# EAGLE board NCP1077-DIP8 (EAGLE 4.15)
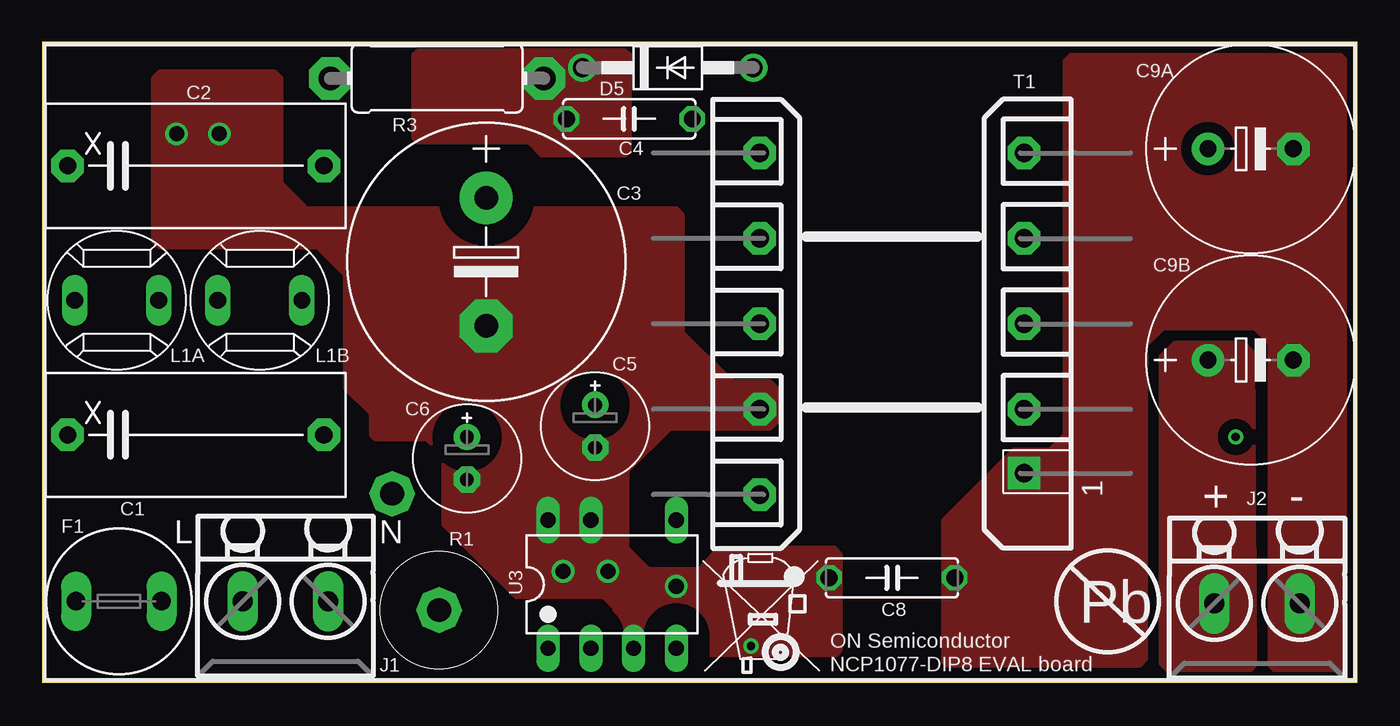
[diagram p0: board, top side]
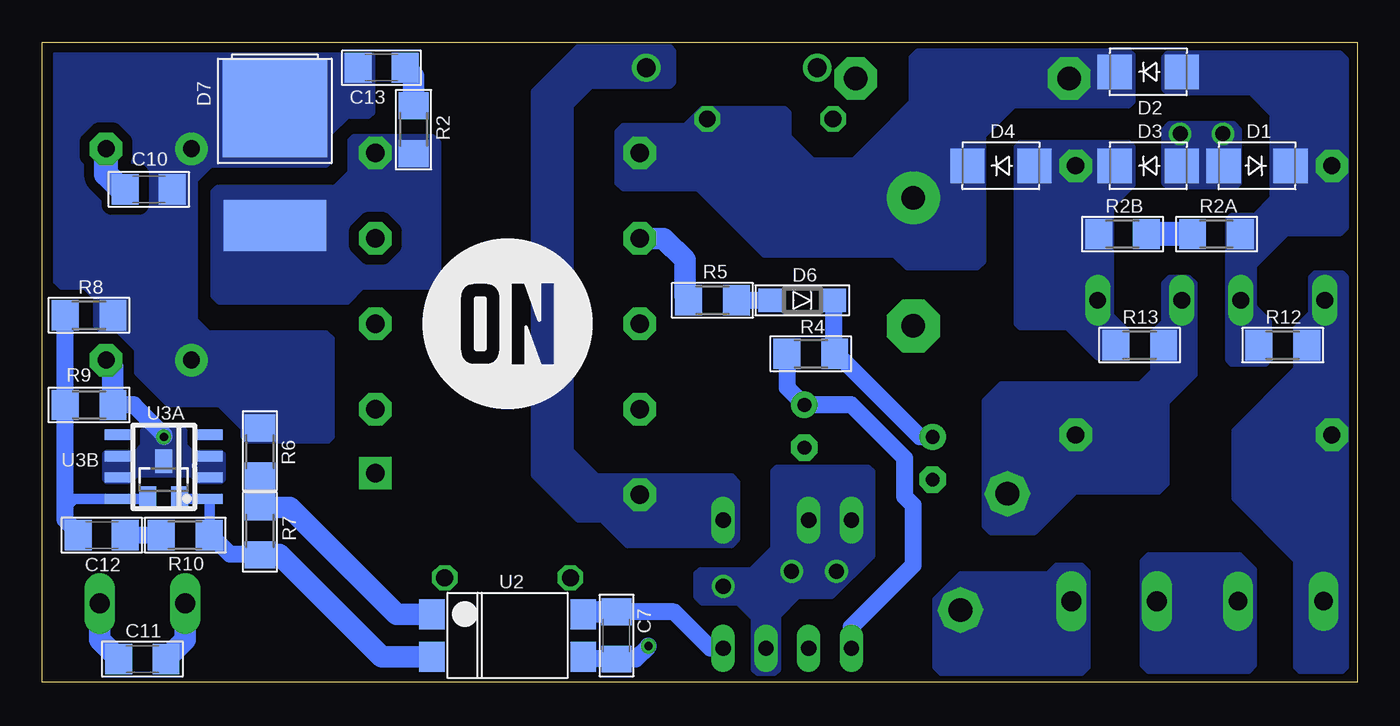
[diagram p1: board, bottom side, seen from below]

Size 78.23 x 38.1 mm. Coordinates in mm from the lower left corner, seen from the top.
Outline: 0,0 78.23,0 78.23,38.1 0,38.1 0,0
Copper layers (1*16): Top 0.035mm / dielectric 1.5mm / Bottom 0.035mm
Design rules "default": minimum track width 10mil, minimum drill 19mil, track to track 8mil, track to pad 8mil, pad to pad 8mil, via to via 8mil, smd to smd 8mil, copper to edge 5mil, drill to drill 8mil, minimum pad ring 10mil, minimum via ring 8mil, stop-mask expansion 4mil, vias tented up to drill 0mil, thermal gap 10mil

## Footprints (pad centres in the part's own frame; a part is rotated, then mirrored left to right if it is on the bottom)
XC18B7.5LS15 = drill 1.016 pad 1.93 octagon: 1 -7.62,0; 2 7.62,0
E7,5-16 = drill 1.4 pad 3.15 round: + -3.81,0 | drill 1.4 pad 3.15 octagon: - 3.81,0
C075-025X080 = drill 1 octagon: 1 -3.74,0; 2 3.74,0
E2.5-6.5 = drill 0.813 pad 1.575 round: + -1.27,0 | drill 0.813 pad 1.575 octagon: - 1.27,0
C1206 = smd 1.6 x 1.8: 1 -1.4,0; 2 1.4,0
E5-12,5 = drill 1 pad 1.93 round: + -2.54,0 | drill 1 pad 1.93 octagon: - 2.54,0
SMA-DIODE = smd 2.032 x 2.032: A 1.994,0; C -1.994,0
DO41-10 = drill 1.118 round: A 5.08,0; C -5.08,0
SOD123 = smd 1.4 x 1.4: A 1.9,0; C -1.9,0
DPAK-SCHOTTKY-2PADS = smd 3.048 x 6.096: 1 2.54,0 | smd 5.791 x 6.198: 4 -4.42,0
TR5 = drill 1.1 pad 1.778 long: 1 -2.54,0; 2 2.54,0
2-PIN = drill 1.2 long: + -2.54,0; - 2.54,0
WE-7447728215 = drill 1 long: P$1 -2.5,0; P$2 2.5,0
3W-STAND-UP = drill 1.4 pad 2.54 octagon: P$1 3.75,0; P$2 -3.71,0
R1206 = smd 1.6 x 1.803: 1 -1.422,0; 2 1.422,0
0411/12 = drill 1.4 pad 2.54 octagon: 1 -6.35,0; 2 6.35,0
E25/10/6-10P = drill 1.1 pad 1.93 square: 1 -8.89,-7.85 | drill 1.1 pad 1.93 octagon: 2 -5.08,-7.85; 3 0,-7.85; 4 5.08,-7.85; 5 10.16,-7.85; 6 10.16,7.85; 7 5.08,7.85; 8 0,7.85; 9 -5.08,7.85; 10 -10.16,7.85
4PIN-SURFMOUNT-OPTO = smd 1.524 x 1.778: 1 4.496,-1.27; 2 4.496,1.27; 3 -4.496,1.27; 4 -4.496,-1.27
DIP07 = drill 0.9 long: 1 -3.81,-3.81; 2 -1.27,-3.81; 3 1.27,-3.81; 4 3.81,-3.81; 5 3.81,3.81; 7 -1.27,3.81; 8 -3.81,3.81
SOT-23 = smd 1 x 1.4: 1 -0.95,-1.1; 2 0.95,-1.1; 3 0,1.1
SOIC-8 = smd 0.61 x 1.524: 1 -1.905,-2.743; 2 -0.635,-2.743; 3 0.635,-2.743; 4 1.905,-2.743; 5 1.905,2.743; 6 0.635,2.743; 7 -0.635,2.743; 8 -1.905,2.743

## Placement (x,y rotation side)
C1  100nF  [XC18B7.5LS15]  9.14,14.73 0 top
C2  100nF  [XC18B7.5LS15]  9.14,30.73 0 top
C3  22uF  [E7,5-16]  26.42,25.02 270 top
C4  1nF  [C075-025X080]  34.93,33.53 180 top
C5  22uF  [E2.5-6.5]  32.89,15.24 270 top
C6  4.7uF  [E2.5-6.5]  25.27,13.34 270 top
C7  1nF  [C1206]  44.07,2.79 270 bottom
C8  1nF  [C075-025X080]  50.55,6.22 0 top
C9A  1000uF  [E5-12,5]  71.88,31.75 0 top
C9B  1000uF  [E5-12,5]  71.88,19.18 0 top
C10  100nF  [C1206]  71.88,29.34 180 bottom
C11  100nF  [C1206]  72.26,1.4 180 bottom
C12  100nF  [C1206]  74.68,8.76 180 bottom
C13  1nF  [C1206]  58.04,36.58 180 bottom
D1  MRA4007  [SMA-DIODE]  5.97,30.73 180 bottom
D2  MRA4007  [SMA-DIODE]  12.45,36.32 0 bottom
D3  MRA4007  [SMA-DIODE]  12.45,30.73 0 bottom
D4  MRA4007  [SMA-DIODE]  21.21,30.73 0 bottom
D5  1N4937  [DO41-10]  37.21,36.58 0 top
D6  MMSD4148A  [SOD123]  33.02,22.73 180 bottom
D7  MBRS3100  [DPAK-SCHOTTKY-2PADS]  64.39,29.72 270 bottom
E$2  [ON2]  50.55,21.34 0 bottom
F1  1.5A  [TR5]  4.57,4.83 180 top
J1  [2-PIN]  14.48,4.83 0 top
J2  [2-PIN]  72.26,4.7 0 top
L1A  1mH  [WE-7447728215]  4.45,22.73 0 top
L1B  1mH  [WE-7447728215]  12.95,22.73 0 top
R1  4.3/3W  [3W-STAND-UP]  22.23,7.75 112 top
R2  47  [R1206]  56.13,32.89 270 bottom
R2A  3.3M  [R1206]  8.38,26.67 0 bottom
R2B  3.3M  [R1206]  13.97,26.67 0 bottom
R3  68K  [0411/12]  23.5,35.94 180 top
R4  2.7K  [R1206]  32.51,19.56 180 bottom
R5  10  [R1206]  38.35,22.73 0 bottom
R6  1K  [R1206]  65.28,13.72 270 bottom
R7  10K  [R1206]  65.28,9.02 270 bottom
R8  82.5K  [R1206]  75.44,21.84 0 bottom
R9  10K  [R1206]  75.44,16.51 180 bottom
R10  21.5K  [R1206]  69.72,8.76 0 bottom
R12  5.6K  [R1206]  4.45,20.07 0 bottom
R13  5.6K  [R1206]  12.95,20.07 0 bottom
T1  [E25/10/6-10P]  50.55,21.34 90 top
U2  PS2561L_1  [4PIN-SURFMOUNT-OPTO]  50.55,2.79 180 bottom
U3  NCP1077  [DIP07]  33.91,5.84 0 top
U3A  NCP431A  [SOT-23]  70.99,12.07 0 bottom
U3B  NCP431A  [SOIC-8]  70.99,12.83 90 bottom
U$3  [WEEE_SMALL]  42.93,1.91 0 top

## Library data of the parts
C1-C8 C9A C9B C10-C13 R2 R2A R2B R3-R10 R12 R13 = rcl
D1-D7 = diode
E$2 = loga
F1 = fuse
J1 J2 = My CONNECTOR lib
L1A L1B = MY  INDUCTOR Lib
R1 = resistor-power
T1 = My X-former
U2 = optocoupler
U3 U3A U3B = My IC Lib
U$3 = My Sign Lib

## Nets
N$1: C1.1 F1.2 L1A.P$1 R12.2
N$2: F1.1 J1.+
N$3: C2.1 D1.C D2.A L1A.P$2 R2A.2 R12.1
N$4: C1.2 L1B.P$1 R1.P$1 R13.2
N$5: J1.- R1.P$2
N$6: C2.2 D3.C D4.A L1B.P$2 R2B.1 R13.1
N$7: R2A.1 R2B.2
N$8: C13.1 R2.1
N$9: D5.A T1.10 U3.5
N$10: C3.+ C4.1 D2.C D4.C R3.2 T1.6
N$11: C4.2 D5.C R3.1
N$13: C5.+ R4.2 U3.1
N$14: C12.1 R10.1
N$15: R7.2 R10.2 U2.2 U3A.2 U3B.1
N$18: R5.1 T1.7
N$19: D6.A R5.2
N$20: C6.+ D6.C R4.1
N$21: C7.1 U2.4 U3.4
N$23: R6.2 R7.1 U2.1
N$24: C12.2 R8.1 R9.2 U3A.1 U3B.8
N$25: D7.1 R2.2 T1.5
N$28: C8.2 C9A.- C9B.- C10.2 C11.2 J2.- R9.1 T1.1 U3A.3 U3B.2 U3B.3 U3B.6 U3B.7
N$30: C9A.+ C9B.+ C10.1 C11.1 C13.2 D7.4 J2.+ R6.1 R8.2
N$44: C3.- C5.- C6.- C7.2 C8.1 D1.A D3.A T1.9 U2.3 U3.3 U3.7 U3.8

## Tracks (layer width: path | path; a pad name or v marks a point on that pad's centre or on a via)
N$1
  pour Bottom (no thermals): 3.68,7.24 3.68,0.89 3.43,0.64 0.89,0.64 0.64,0.89 0.64,24.13 0.89,24.38 2.54,24.38 2.79,24.13 2.79,21.97 3.68,21.08 3.68,18.67 7.37,14.99 7.37,10.92
N$2
  pour Bottom (no thermals): 6.1,1.02 6.1,6.73 6.99,7.62 12.45,7.62 12.83,7.24 12.83,1.02 12.45,0.64 6.48,0.64
N$3
  pour Bottom (no thermals): 6.1,22.35 6.1,24.77 4.19,26.67 1.02,26.67 0.64,27.05 0.64,37.08 1.02,37.47 11.3,37.47 11.56,37.21 11.56,35.31 11.3,35.05 6.35,35.05 5.08,33.78 5.08,28.83 6.1,27.81 7.49,27.81 7.75,27.56 7.75,19.18 7.49,18.92 5.46,18.92 5.21,19.18 5.21,21.46
N$4
  pour Bottom (no thermals): 16.76,11.3 19.18,8.89 21.84,8.89 22.23,9.27 22.23,16.76 21.21,17.78 12.95,17.78 12.19,18.54 12.19,20.83 11.56,21.46 11.56,23.75 11.18,24.13 10.03,24.13 9.65,23.75 9.65,18.29 11.3,16.64 11.3,11.81 11.81,11.3
N$5
  pour Bottom (no thermals): 16,6.6 16,0.89 16.38,0.51 24.77,0.51 25.15,0.89 25.15,4.95 23.62,6.48 18.42,6.48 17.91,6.99 16.38,6.99
N$6
  pour Bottom (no thermals): 14.61,21.84 14.61,28.32 13.34,29.59 13.34,31.88 13.59,32.13 20.07,32.13 20.32,31.88 20.32,21.34 20.07,21.08 17.27,21.08 15.49,19.3 13.97,19.3 13.72,19.56 13.72,20.96
N$7
  Bottom 1.422: R2A.1 R2B.2
N$8
  Bottom 1.27: C13.1 56.13,36.07 R2.1
N$9
  pour Bottom (no thermals): 37.21,12.32 45.21,12.32 46.74,13.84 46.74,34.29 45.59,35.43 40.89,35.43 40.64,35.69 40.64,37.59 40.89,37.85 46.36,37.85 49.02,35.18 49.02,12.32 46.36,9.65 44.96,9.65 43.43,8.13 37.21,8.13 36.83,8.51 36.83,11.94
N$10
  pour Bottom (no thermals): 13.59,37.59 26.16,37.59 26.54,37.21 26.54,34.54 28.83,32.26 29.97,31.12 32.39,31.12 33.78,32.51 33.78,33.91 34.04,34.16 38.99,34.16 40.01,33.15 43.69,33.15 44.07,32.77 44.07,29.72 43.69,29.34 39.24,29.34 35.31,25.4 27.56,25.4 26.8,24.64 22.61,24.64 22.23,25.02 22.23,32.51 20.45,34.29 13.59,34.29 13.34,34.54 13.34,37.34
N$11
  pour Top (no thermals): 22.35,37.59 34.67,37.59 34.93,37.34 34.93,31.62 34.67,31.37 29.72,31.37 28.96,32.13 22.35,32.13 22.1,32.39 22.1,37.34
N$13
  Bottom 1.016: U3.1 30.1,3.3 26.42,6.99 26.42,10.54 26.92,11.05 26.92,13.34 30.1,16.51 C5.+ 33.91,17.53 33.91,19.56 R4.2
N$14
  Bottom 1.016: C12.1 R10.1
N$15
  Bottom 0.61: U3A.2 70.02,10.97 69.98,10.92 U3B.1 68.25,8.84 68.33,8.76 R10.2
  Bottom 1.016: R10.2 68.2,8.76 67.06,7.62 65.28,7.62
  Bottom 1.27: 65.28,7.62 65.15,7.75 | U2.2 58.04,1.52 64.14,7.62 65.28,7.62 | 65.28,7.62 R7.2
N$18
  Bottom 1.27: T1.7 41.28,26.42 40.01,25.15 40.01,22.99 39.75,22.73 R5.1
N$19
  Bottom 1.016: R5.2 36.83,22.73 D6.A
  Bottom 1.27: D6.A
N$20
  Bottom 1.016: D6.C 31.12,19.56 R4.1 30.99,19.56 26.04,14.61 C6.+
N$21
  Bottom 1.016: U3.4 38.48,2.03 40.64,4.19 C7.1
  Bottom 1.27: U2.4 45.97,4.06 45.84,4.19 C7.1
N$23
  Bottom 1.016: R7.1 65.28,10.41
  Bottom 1.27: 65.28,10.41 65.15,10.29 | 65.28,12.32 R6.2 R7.1 65.18,10.44 65.15,10.41 63.5,10.41 57.15,4.06 U2.1
N$24
  Bottom 0.61: U3A.1 71.97,10.97 72.01,10.92 U3B.8 76.33,10.92 76.84,10.41 76.86,10.41
  Bottom 1.016: R8.1 76.86,16.54 76.84,16.51 R9.2 76.86,10.41 76.86,9.68 76.07,8.89 76.08,8.89 C12.2
N$25
  pour Bottom (isolate 0.61, no thermals): 60.07,22.61 59.18,23.5 54.99,23.5 54.61,23.88 54.61,32.13 54.99,32.51 59.69,32.51 59.94,32.26 59.94,30.35 60.83,29.46 67.82,29.46 68.07,29.21 68.07,22.99 67.69,22.61
N$28  (via drill 0.5)
  Bottom 1.016: v70.99,14.61 70.99,14.73 72.77,16.51 R9.1 74.04,16.51
  Bottom 1.27: C11.2 74.8,2.54 J2.- | R9.1 74.02,18.77 C9B.-
  Bottom 1.422: C10.2 73.53,29.34 74.42,30.23 C9A.-
  pour Bottom (no thermals): 67.44,12.07 67.44,13.59 67.56,13.72 69.34,13.72 69.72,14.1 69.72,14.99 69.85,15.11 72.14,15.11 72.26,14.99 72.26,14.1 72.64,13.72 74.42,13.72 74.55,13.59 74.55,12.07 74.42,11.94 73.03,11.94 72.64,12.32 69.34,12.32 68.96,11.94 67.56,11.94
  pour Top (isolate 0.61, no thermals): 60.83,14.73 60.83,36.96 61.21,37.34 77.22,37.34 77.47,37.08 77.47,1.02 77.22,0.76 73.28,0.76 73.03,1.02 73.03,20.19 72.14,21.08 66.68,21.08 65.66,20.07 65.66,1.4 65.28,1.02 53.85,1.02 53.59,1.27 53.59,9.65 57.79,13.84 59.94,13.84
N$30
  Bottom 1.27: C11.1 69.72,2.54 J2.+
  pour Bottom (isolate 0.61, no thermals): 58.8,37.59 77.22,37.59 77.47,37.34 77.47,23.88 77.09,23.5 75.69,23.5 75.06,22.86 75.06,21.21 74.8,20.96 73.79,20.96 72.64,19.81 72.64,18.42 70.74,16.51 67.69,16.51 66.29,15.11 66.29,14.61 66.04,14.35 61.21,14.35 60.96,14.61 60.96,20.45 61.34,20.83 68.33,20.83 69.09,21.59 69.09,29.85 68.2,30.73 61.34,30.73 61.09,30.99 61.09,32.64 60.07,33.66 58.8,33.66 58.55,33.91 58.55,37.34
  pour Top (isolate 0.61, rank 2, no thermals): 71.88,0.76 66.93,0.76 66.55,1.14 66.55,19.81 66.93,20.19 71.63,20.19 72.01,19.81 72.14,1.02
N$44  (via drill 0.5, 0.9)
  Bottom 1.016: v42.16,2.16 42.93,1.39 C7.2 45.97,1.39 46.1,1.52 U2.3
  other vias: 8,32.64 10.54,32.64 30.99,6.6 33.66,6.6 37.72,5.72
  pour Bottom (no thermals): 6.99,29.85 6.99,32.89 7.37,33.27 11.18,33.27 11.56,32.89 11.56,29.72 11.3,29.46 7.24,29.46 6.99,29.72 6.99,31.24
  pour Bottom (no thermals): 29.08,12.83 34.54,12.83 34.8,12.57 34.8,8 36.07,6.73 39.12,6.73 39.37,6.48 39.37,5.08 38.99,4.7 36.83,4.7 35.94,3.81 35.94,0.76 35.69,0.51 34.67,0.51 34.42,0.76 34.42,3.94 33.27,5.08 31.24,5.08 28.83,7.49 28.83,12.57
  pour Top (isolate 1.27, no thermals): 6.6,35.94 6.6,26.29 6.99,25.91 16.38,25.91 18.03,24.26 18.03,17.53 19.56,16 19.56,14.73 19.81,14.48 22.86,14.48 23.88,13.46 23.88,9.4 28.19,5.08 33.4,5.08 34.04,4.45 34.04,2.16 34.54,1.65 47.24,1.65 47.5,1.91 47.5,7.62 47.12,8 40.26,8 39.12,6.73 36.07,6.73 34.8,8 34.8,12.57 37.34,15.11 43.31,15.11 43.69,15.49 43.69,17.53 43.31,17.91 41.02,17.91 38.1,20.83 38.1,27.81 37.72,28.19 15.75,28.19 14.22,29.72 14.22,35.94 13.84,36.32 6.99,36.32

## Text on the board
tPlace: + | - | L | N | Pb | ON Semiconductor | NCP1077-DIP8 EVAL board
